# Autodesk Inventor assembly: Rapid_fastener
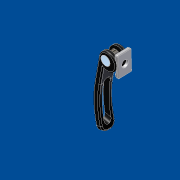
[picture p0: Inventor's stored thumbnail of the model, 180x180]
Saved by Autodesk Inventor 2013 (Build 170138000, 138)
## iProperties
Shininess: 20.0
Length Units: 11269
Angle Units: 11279
Time Units: 11290
Mass Units: 11283
Length Display Precision: 3
Angle Display Precision: 2
Created: 2001-04
Part Number: Rapid_fastener
Document SubType Name: Baugruppe
Designer: dl
Density: 0.0
Volumn: 0.0
Area: 0.0
PropertySet Name: Model Information
Control State: 0
Master: False
Checked Out: False
Author: dl
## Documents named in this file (4)
- C:\Webworld\Webworld2014\ATC2013\Assemblies\ATC-Baby Carriage\CLAMPDAMPER\Rapid_fastener.iam
- C:\Webworld\Webworld2014\ATC2013\Assemblies\ATC-Baby Carriage\CLAMPDAMPER\Lever.ipt
- C:\Webworld\Webworld2014\ATC2013\Assemblies\ATC-Baby Carriage\CLAMPDAMPER\Nut1.ipt
- C:\Webworld\Webworld2014\ATC2013\Assemblies\ATC-Baby Carriage\CLAMPDAMPER\Washer.ipt
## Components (3 placed, 3 different names)
1. Lever:1 — Mate:1, Flush:1
2. Nut1:1 — Mate:1, Flush:1, Flush:2, Mate:2
3. Washer:1 — Flush:2, Mate:2
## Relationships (4: Mate 2, Flush 2)
- Mate:1: Lever:1 ↔ Nut1:1
- Flush:1: Lever:1 ↔ Nut1:1
- Flush:2: Nut1:1 ↔ Washer:1
- Mate:2: Nut1:1 ↔ Washer:1
